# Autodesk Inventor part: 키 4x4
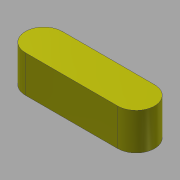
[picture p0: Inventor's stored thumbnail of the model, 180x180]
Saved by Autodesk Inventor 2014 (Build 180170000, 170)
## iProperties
Created: 2016-04
Part Number: 키 4x4
Document SubType Name: Modeling
Designer: mdu
Density: 7.86 g/cm^3
Mass: 1.65269 g
Surface Area: 2.35398 cm^2
Volume: 0.210265 cm^3
Material: 강철, 연강
Appearance: 강철 - 광택
Author: mdu
Revision Number: 1
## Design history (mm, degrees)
sketch "스케치1"
  geometry: L1 (-5, -2)-(5, -2); L2 (5, 2)-(-5, 2); A1 r 2 centre (5, 0) between (5, -2) and (5, 2); A2 r 2 centre (-5, 0) between (-5, 2) and (-5, -2); 2 further points
  constraints: 4 end point, 4 point on circle, 4 tangent, 2 centre point, 1 horizontal, 1 horizontal alignment, 1 midpoint, 1 parallel, 1 vertical alignment
  dimensions: "d0" = 4 distance between parallel lines of L1 L2; "d1" = 14 dimension on A1 A2
extrude "돌출1" new body sketch "스케치1" stored distance "d2" = 4; taper "d3" = 0 deg
node "솔리드1"
